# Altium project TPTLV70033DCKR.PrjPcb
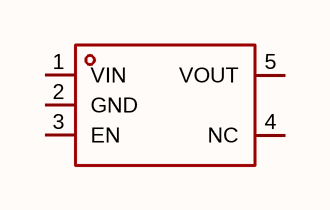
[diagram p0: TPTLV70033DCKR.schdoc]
1 sheet, 1 parts. Net scope: global (net labels, ports and power ports of the same name join across sheets).

## Sheet TPTLV70033DCKR.schdoc
size 127 x 101 mm

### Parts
U?  tptlv70033dckr  [SC-70-5_L2.1-W1.3-P0.65-LS2.2-BR]  (value not drawn)

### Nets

Not connected (* = marked no-connect by the designer): U? 1(VIN) 2(GND) 3(EN) 4(NC) 5(VOUT)

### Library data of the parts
U? = tptlv70033dckr: 输出极性:正极;工作电压:5.5V;输出电压:3.3V;输出电流:300mA;电源纹波抑制比(PSRR):75dB@(1kHz);输出类型:固定;; Manufacturer: TECH PUBLIC(台舟); AddInBom: yes; ModelId: bbbea4ffa64849e5a6867c90e2cb6619; ModelTransform: 82.677,78.74,0,0,0,0,0,0,0; Output Configuration: 正极; Voltage - Supply: 5.5V; Output Voltage: 3.3V; Output Current: 300mA; Voltage Dropout: 200mV@(300mA); standby current: 20uA; Noise: 51uVrms; Output Type: 固定; Number of Outputs: 1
